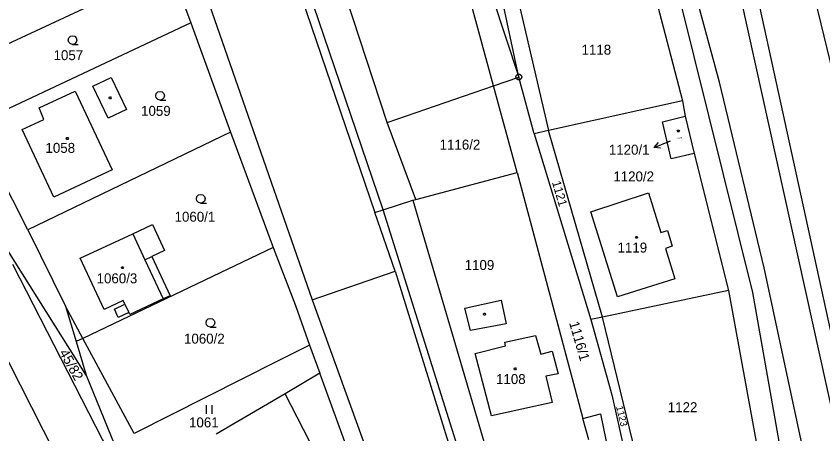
# Model space of a CAD drawing. Extents: x -609861 to -605046, y -1120287 to -1116307.
# Drawn here: x -607474 to -607336.2, y -1118831.6 to -1118760.2 of the extents above; entities that cross this region are included whole.
import ezdxf

# ---------------------------------------------------------------- set-up
doc = ezdxf.new("R2010")
doc.units = 0
for name, color, linetype in [('Vrstva 1', 7, 'Continuous'), ('Vrstva 2', 7, 'Continuous'), ('Vrstva 3', 7, 'Continuous'), ('Vrstva 4', 7, 'Continuous'), ('Vrstva 5', 7, 'Continuous'), ('Vrstva 7', 7, 'Continuous'), ('Vrstva 8', 7, 'Continuous')]:
    doc.layers.add(name, color=color, linetype=linetype)

msp = doc.modelspace()

# ---------------------------------------------------------------- linework, layer by layer
at = {"layer": 'Vrstva 1'}
for p, q in [((-607410.59, -1118778.4), (-607447.19, -1118667.29)), ((-607454.93, -1118669.66), (-607412.72, -1118793.79)), ((-607469.9, -1118675.06), (-607423.44, -1118808.75)), ((-607334.37, -1118770.22), (-607346.49, -1118719.95)), ((-607353.53, -1118742.27), (-607332.92, -1118835.44)), ((-607392.43, -1118772.13), (-607400.04, -1118744.15)), ((-607368.13, -1118744.34), (-607360.18, -1118774.7)), ((-607350.09, -1118744.65), (-607330.35, -1118835.05)), ((-607396.32, -1118745.75), (-607388.14, -1118770.65)), ((-607447.58, -1118751.93), (-607485.33, -1118769.67)), ((-607447.58, -1118751.93), (-607444.13, -1118761.4)), ((-607348.15, -1118807.47), (-607361.89, -1118752.25)), ((-607444.13, -1118761.4), (-607481.13, -1118778.79)), ((-607444.13, -1118761.4), (-607437.37, -1118780.09)), ((-607392.43, -1118772.13), (-607388.14, -1118770.65)), ((-607385.52, -1118780.34), (-607388.14, -1118770.65)), ((-607410.59, -1118778.4), (-607392.43, -1118772.13)), ((-607388.4, -1118786.96), (-607392.43, -1118772.13)), ((-607470.07, -1118775.94), (-607463.88, -1118773.05)), ((-607463.88, -1118773.05), (-607457.6, -1118786.52)), ((-607360.18, -1118774.7), (-607383.08, -1118779.8)), ((-607360.18, -1118774.7), (-607359.71, -1118777.36)), ((-607469.27, -1118777.89), (-607470.07, -1118775.94)), ((-607363.6, -1118778.31), (-607359.71, -1118777.36)), ((-607359.71, -1118777.36), (-607358.18, -1118783.7)), ((-607472.98, -1118779.62), (-607469.27, -1118777.89)), ((-607405.72, -1118791.57), (-607410.59, -1118778.4)), ((-607362.1, -1118784.63), (-607363.6, -1118778.31)), ((-607467.56, -1118791.16), (-607472.98, -1118779.62)), ((-607437.37, -1118780.09), (-607471.97, -1118796.75)), ((-607437.37, -1118780.09), (-607430.07, -1118799.78)), ((-607383.08, -1118779.8), (-607385.52, -1118780.34)), ((-607385.52, -1118780.34), (-607375.82, -1118812.1)), ((-607373.86, -1118811.69), (-607383.08, -1118779.8)), ((-607358.18, -1118783.7), (-607362.1, -1118784.63)), ((-607358.18, -1118783.7), (-607352.3, -1118807.14)), ((-607471.97, -1118796.75), (-607477.97, -1118784.99)), ((-607457.6, -1118786.52), (-607467.56, -1118791.16)), ((-607405.72, -1118791.57), (-607388.4, -1118786.96)), ((-607388.4, -1118786.96), (-607377.17, -1118829.02)), ((-607406.21, -1118791.7), (-607405.72, -1118791.57)), ((-607375.83, -1118793.7), (-607365.99, -1118790.46)), ((-607365.99, -1118790.46), (-607363.88, -1118797.23)), ((-607411.31, -1118793.33), (-607406.21, -1118791.7)), ((-607406.21, -1118791.7), (-607392.89, -1118837.08)), ((-607412.72, -1118793.79), (-607411.31, -1118793.33)), ((-607409.23, -1118803.85), (-607412.72, -1118793.79)), ((-607382.19, -1118886.21), (-607411.31, -1118793.33)), ((-607371.28, -1118808.21), (-607375.83, -1118793.7)), ((-607471.97, -1118796.75), (-607465.54, -1118809.84)), ((-607454.06, -1118797.43), (-607450.7, -1118795.87)), ((-607450.7, -1118795.87), (-607448.63, -1118800.31)), ((-607363.88, -1118797.23), (-607362.73, -1118796.89)), ((-607362.73, -1118796.89), (-607361.92, -1118799.57)), ((-607462, -1118821.61), (-607477, -1118797.84)), ((-607463.03, -1118801.61), (-607454.06, -1118797.43)), ((-607430.07, -1118799.78), (-607462.58, -1118815.33)), ((-607430.07, -1118799.78), (-607426.27, -1118809.73)), ((-607361.92, -1118799.57), (-607363.09, -1118799.95)), ((-607448.63, -1118800.31), (-607450.81, -1118801.33)), ((-607363.09, -1118799.95), (-607361.51, -1118805.12)), ((-607465.69, -1118838.13), (-607484.42, -1118801.47)), ((-607474.63, -1118802.61), (-607457.47, -1118836.07)), ((-607458.94, -1118810.39), (-607463.03, -1118801.61)), ((-607450.81, -1118801.33), (-607447.68, -1118808.03)), ((-607423.44, -1118808.75), (-607409.23, -1118803.85)), ((-607409.23, -1118803.85), (-607388.67, -1118870.31)), ((-607361.51, -1118805.12), (-607371.28, -1118808.21)), ((-607447.68, -1118808.03), (-607448.86, -1118808.58)), ((-607352.3, -1118807.14), (-607373.86, -1118811.69)), ((-607352.3, -1118807.14), (-607345.84, -1118842.76)), ((-607341.92, -1118842.84), (-607348.15, -1118807.47)), ((-607455.69, -1118808.84), (-607458.94, -1118810.39)), ((-607457.21, -1118810.32), (-607455.4, -1118809.48)), ((-607455.4, -1118809.48), (-607455.69, -1118808.84)), ((-607448.86, -1118808.58), (-607454.57, -1118811.24)), ((-607423.44, -1118808.75), (-607399.84, -1118873.88)), ((-607465.54, -1118809.84), (-607463.73, -1118815.87)), ((-607456.55, -1118811.73), (-607457.21, -1118810.32)), ((-607454.74, -1118810.88), (-607456.55, -1118811.73)), ((-607454.57, -1118811.24), (-607454.74, -1118810.88)), ((-607426.27, -1118809.73), (-607423.88, -1118816.46)), ((-607373.86, -1118811.69), (-607375.82, -1118812.1)), ((-607375.82, -1118812.1), (-607372.24, -1118824.96)), ((-607365.35, -1118846.62), (-607373.86, -1118811.69)), ((-607390.53, -1118815.97), (-607385.27, -1118814.83)), ((-607385.27, -1118814.83), (-607384.37, -1118818.03)), ((-607462.58, -1118815.33), (-607463.73, -1118815.87)), ((-607463.73, -1118815.87), (-607462, -1118821.61)), ((-607453.82, -1118831.58), (-607462.58, -1118815.33)), ((-607390.43, -1118816.62), (-607390.53, -1118815.97)), ((-607423.88, -1118816.46), (-607429.24, -1118819.17)), ((-607423.88, -1118816.46), (-607422.09, -1118821.29)), ((-607395.56, -1118817.9), (-607390.43, -1118816.62)), ((-607384.37, -1118818.03), (-607382.42, -1118817.51)), ((-607382.42, -1118817.51), (-607381.4, -1118821.37)), ((-607429.24, -1118819.17), (-607453.82, -1118831.58)), ((-607392.8, -1118828.57), (-607395.56, -1118817.9)), ((-607462, -1118821.61), (-607455.07, -1118838.59)), ((-607422.09, -1118821.29), (-607428.06, -1118824.8)), ((-607412.86, -1118846.8), (-607422.09, -1118821.29)), ((-607381.4, -1118821.37), (-607383.49, -1118821.81)), ((-607383.49, -1118821.81), (-607382.44, -1118826.3)), ((-607428.06, -1118824.8), (-607439.84, -1118831.72)), ((-607419.59, -1118841.15), (-607428.06, -1118824.8)), ((-607372.24, -1118824.96), (-607367.31, -1118847.01)), ((-607382.44, -1118826.3), (-607392.8, -1118828.57)), ((-607377.17, -1118829.02), (-607374.17, -1118828.22)), ((-607374.17, -1118828.22), (-607363.52, -1118880.2)), ((-607376.19, -1118832.69), (-607377.17, -1118829.02))]:
    msp.add_line(p, q, dxfattribs=at)
msp.add_lwpolyline([(-607411.31, -1118793.33), (-607453.5, -1118669.23), (-607471.98, -1118608.19), (-607487.48, -1118565.33)], dxfattribs=at)
at = {"layer": 'Vrstva 3'}
for p, q in [((-607441.52, -1118826.75), (-607441.52, -1118828.25)), ((-607440.52, -1118828.25), (-607440.52, -1118826.75))]:
    msp.add_line(p, q, dxfattribs=at)
for points in [[(-607464.35, -1118765.06), (-607464.73, -1118764.96), (-607465, -1118764.69), (-607465.1, -1118764.32), (-607465, -1118763.95), (-607464.73, -1118763.68), (-607464.36, -1118763.58), (-607463.99, -1118763.68), (-607463.72, -1118763.95), (-607463.62, -1118764.33), (-607463.72, -1118764.71), (-607463.99, -1118764.98), (-607464.37, -1118765.08), (-607463.37, -1118765.08)], [(-607449.4, -1118774.58), (-607449.78, -1118774.48), (-607450.05, -1118774.21), (-607450.15, -1118773.84), (-607450.05, -1118773.47), (-607449.78, -1118773.2), (-607449.41, -1118773.1), (-607449.04, -1118773.2), (-607448.77, -1118773.47), (-607448.67, -1118773.85), (-607448.77, -1118774.23), (-607449.04, -1118774.5), (-607449.42, -1118774.6), (-607448.42, -1118774.6)], [(-607442.46, -1118792.19), (-607442.84, -1118792.09), (-607443.11, -1118791.82), (-607443.21, -1118791.45), (-607443.11, -1118791.08), (-607442.84, -1118790.81), (-607442.47, -1118790.71), (-607442.1, -1118790.81), (-607441.83, -1118791.08), (-607441.73, -1118791.46), (-607441.83, -1118791.84), (-607442.1, -1118792.11), (-607442.48, -1118792.21), (-607441.48, -1118792.21)], [(-607440.8, -1118813.38), (-607441.18, -1118813.28), (-607441.45, -1118813.01), (-607441.55, -1118812.64), (-607441.45, -1118812.27), (-607441.18, -1118812), (-607440.81, -1118811.9), (-607440.44, -1118812), (-607440.17, -1118812.27), (-607440.07, -1118812.65), (-607440.17, -1118813.03), (-607440.44, -1118813.3), (-607440.82, -1118813.4), (-607439.82, -1118813.4)]]:
    msp.add_lwpolyline(points, dxfattribs=at)
at = {"layer": 'Vrstva 4'}
for p, q in [((-607353.85, -1118771.54), (-607362.62, -1118739)), ((-607390.02, -1118749.86), (-607383.08, -1118779.8)), ((-607388.14, -1118770.65), (-607392.48, -1118750.34)), ((-607460.89, -1118772.2), (-607457.77, -1118770.75)), ((-607457.77, -1118770.75), (-607455.13, -1118776.17)), ((-607458.25, -1118777.69), (-607460.89, -1118772.2)), ((-607346.21, -1118803.25), (-607353.85, -1118771.54)), ((-607455.13, -1118776.17), (-607458.25, -1118777.69)), ((-607454.06, -1118797.43), (-607451.99, -1118801.87)), ((-607451.99, -1118801.87), (-607450.81, -1118801.33)), ((-607451.99, -1118801.87), (-607448.86, -1118808.58)), ((-607338.78, -1118838.1), (-607346.21, -1118803.25)), ((-607455.4, -1118809.48), (-607454.74, -1118810.88)), ((-607397.36, -1118810.16), (-607391.16, -1118808.81)), ((-607391.16, -1118808.81), (-607390.29, -1118812.81)), ((-607462.58, -1118815.33), (-607465.54, -1118809.84)), ((-607396.39, -1118814), (-607397.36, -1118810.16)), ((-607390.29, -1118812.81), (-607396.39, -1118814))]:
    msp.add_line(p, q, dxfattribs=at)
at = {"layer": 'Vrstva 5'}
for points in [[(-607457.85, -1118774.06), (-607457.76, -1118774.21), (-607457.85, -1118774.36), (-607458.03, -1118774.36), (-607458.12, -1118774.21), (-607458.03, -1118774.06)], [(-607360.8, -1118779.74), (-607360.71, -1118779.89), (-607360.8, -1118780.04), (-607360.98, -1118780.04), (-607361.07, -1118779.89), (-607360.98, -1118779.74)], [(-607465.16, -1118781.01), (-607465.07, -1118781.16), (-607465.16, -1118781.31), (-607465.34, -1118781.31), (-607465.43, -1118781.16), (-607465.34, -1118781.01)], [(-607367.93, -1118797.9), (-607367.84, -1118798.05), (-607367.93, -1118798.2), (-607368.11, -1118798.2), (-607368.2, -1118798.05), (-607368.11, -1118797.9)], [(-607455.74, -1118803.07), (-607455.65, -1118803.22), (-607455.74, -1118803.37), (-607455.92, -1118803.37), (-607456.01, -1118803.22), (-607455.92, -1118803.07)], [(-607393.9, -1118811.04), (-607393.81, -1118811.19), (-607393.9, -1118811.34), (-607394.08, -1118811.34), (-607394.17, -1118811.19), (-607394.08, -1118811.04)], [(-607388.68, -1118820.38), (-607388.59, -1118820.53), (-607388.68, -1118820.68), (-607388.86, -1118820.68), (-607388.95, -1118820.53), (-607388.86, -1118820.38)]]:
    msp.add_lwpolyline(points, close=True, dxfattribs=at)
at = {"layer": 'Vrstva 7'}
msp.add_line((-607365.032, -1118782.702), (-607362.25, -1118781.58), dxfattribs=at)
msp.add_lwpolyline([(-607363.918, -1118782.792), (-607365.032, -1118782.702), (-607364.292, -1118781.864)], dxfattribs=at)
at = {"layer": 'Vrstva 8'}
msp.add_line((-607388.26, -1118770.65), (-607388.02, -1118770.65), dxfattribs=at)
msp.add_lwpolyline([(-607387.99, -1118770.17), (-607387.74, -1118770.35), (-607387.64, -1118770.64), (-607387.74, -1118770.93), (-607387.99, -1118771.11), (-607388.3, -1118771.11), (-607388.55, -1118770.93), (-607388.65, -1118770.64), (-607388.55, -1118770.35), (-607388.3, -1118770.17)], close=True, dxfattribs=at)

# ---------------------------------------------------------------- texts
at = {"layer": 'Vrstva 2'}
for s, height, p in [('1118', 1.7, (-607377.417, -1118766.82)), ('1057', 1.7, (-607467.597, -1118767.76)), ('1059', 1.7, (-607452.647, -1118777.28)), ('1058', 1.7, (-607468.977, -1118783.61)), ('1116/2', 1.7, (-607401.657, -1118783.05)), ('1120/1', 0.2, (-607361.064, -1118781.1)), ('1120/2', 1.7, (-607371.987, -1118788.49)), ('1060/1', 1.7, (-607446.927, -1118795.38)), ('1119', 1.7, (-607371.267, -1118800.65)), ('1109', 1.7, (-607397.377, -1118803.63)), ('1060/3', 1.7, (-607460.247, -1118805.91)), ('1060/2', 1.7, (-607445.317, -1118816.22)), ('1108', 1.7, (-607392.017, -1118823.13)), ('1122', 1.7, (-607362.687, -1118827.94)), ('1061', 1.7, (-607444.457, -1118830.54))]:
    msp.add_text(s, height=height, dxfattribs=at).set_placement(p)
for s, height, rotation, p in [('1121', 1.5, 286.19242, (-607382.483, -1118788.623)), ('1116/1', 1.7, 286.19242, (-607379.56, -1118812.667)), ('45/82', 1.7, 299.37045, (-607466.696, -1118817.76)), ('1123', 1.2, 283.49952, (-607371.535, -1118827.01))]:
    msp.add_text(s, height=height, rotation=rotation, dxfattribs=at).set_placement(p)
at = {"layer": 'Vrstva 7'}
msp.add_text('1120/1', height=1.7, dxfattribs=at).set_placement((-607372.756, -1118783.92))

doc.saveas('drawing.dxf')
